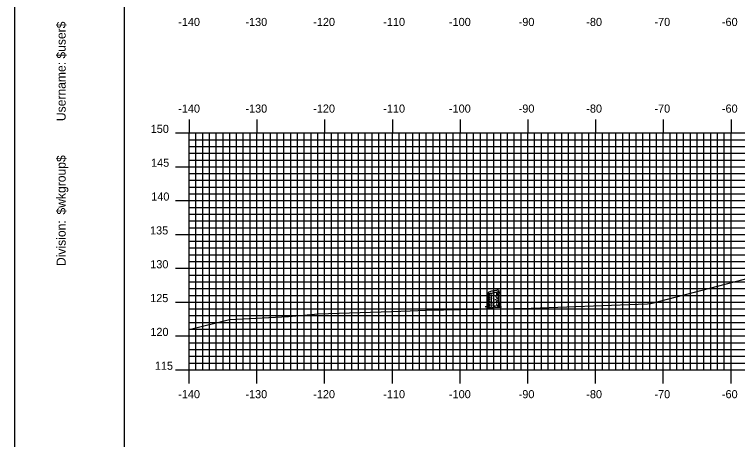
# Model space of a CAD drawing. Extents: x 851753 to 852097, y 364661 to 364881.
# Drawn here: x 851753.5 to 851860.2, y 364724.1 to 364786.9 of the extents above; entities that cross this region are included whole.
import ezdxf

# ---------------------------------------------------------------- set-up
doc = ezdxf.new("R2010")
doc.units = 0
for name, color, linetype in [('BORDER', 7, 'Continuous'), ('H_V ANNOTATION', 7, 'Continuous'), ('M_Trees_Conifer_Pay', 7, 'Continuous'), ('MAJOR', 7, 'Continuous'), ('MINOR', 7, 'Continuous'), ('PLOT BOUNDARY', 7, 'Continuous'), ('S_Roadway_Centerline', 7, 'Continuous')]:
    doc.layers.add(name, color=color, linetype=linetype)

msp = doc.modelspace()

# ---------------------------------------------------------------- linework, layer by layer
at = {"layer": 'BORDER'}
msp.add_lwpolyline([(851769.64, 364667.37), (852089.64, 364667.37), (852089.64, 364877.37), (851769.64, 364877.37)], close=True, dxfattribs=at)
at = {"layer": 'M_Trees_Conifer_Pay'}
for p, q in [((851823.36, 364744.01), (851823.36, 364745.73)), ((851823.41, 364745.69), (851823.41, 364745.22)), ((851823.47, 364745.68), (851823.47, 364745.58)), ((851823.59, 364745.67), (851823.59, 364745.44)), ((851823.81, 364745.69), (851823.81, 364745.52)), ((851824.61, 364745.73), (851824.61, 364745.53)), ((851824.84, 364745.93), (851824.84, 364745.71)), ((851824.84, 364745.62), (851824.84, 364745.57)), ((851824.95, 364745.99), (851824.95, 364745.83)), ((851824.95, 364745.76), (851824.95, 364745.63)), ((851825.02, 364744.42), (851825.02, 364746.06)), ((851823.41, 364745.15), (851823.41, 364744.85)), ((851823.41, 364744.8), (851823.41, 364744.31)), ((851823.47, 364745.51), (851823.47, 364745.3)), ((851823.47, 364745.25), (851823.47, 364745.05)), ((851823.47, 364745), (851823.47, 364744.66)), ((851823.47, 364744.61), (851823.47, 364744.47)), ((851823.59, 364745.4), (851823.59, 364745.32)), ((851823.59, 364744.92), (851823.59, 364744.78)), ((851823.81, 364745.29), (851823.81, 364745.05)), ((851823.81, 364744.8), (851823.81, 364744.65)), ((851823.81, 364744.61), (851823.81, 364744.44)), ((851824.22, 364745.46), (851824.22, 364745.36)), ((851824.22, 364744.85), (851824.22, 364744.77)), ((851824.22, 364744.75), (851824.22, 364744.6)), ((851824.61, 364745.48), (851824.61, 364745.39)), ((851824.61, 364745.04), (851824.61, 364744.93)), ((851824.61, 364744.57), (851824.61, 364744.42)), ((851824.89, 364745.43), (851824.84, 364745.37)), ((851824.84, 364745.24), (851824.84, 364745.1)), ((851824.84, 364744.99), (851824.84, 364744.88)), ((851824.84, 364744.75), (851824.84, 364744.61)), ((851824.95, 364745.45), (851824.95, 364745.11)), ((851824.95, 364745.07), (851824.95, 364744.91)), ((851824.95, 364744.86), (851824.95, 364744.65)), ((851824.95, 364744.62), (851824.95, 364744.54)), ((851823.41, 364744.25), (851823.41, 364744.01)), ((851823.47, 364744.37), (851823.47, 364744)), ((851823.59, 364744.51), (851823.59, 364744.37)), ((851823.59, 364744.11), (851823.59, 364744.01)), ((851823.59, 364743.61), (851823.75, 364743.68)), ((851823.81, 364744.16), (851823.81, 364744.01)), ((851824.03, 364743.55), (851823.9, 364743.61)), ((851824.22, 364744.31), (851824.22, 364744.15)), ((851824.61, 364744.19), (851824.61, 364744.1)), ((851824.84, 364744.38), (851824.84, 364744.21)), ((851824.95, 364744.5), (851824.95, 364744.33))]:
    msp.add_line(p, q, dxfattribs=at)
for points in [[(851824.84, 364745.56), (851824.88, 364745.49), (851824.93, 364745.54), (851824.98, 364745.61), (851825.08, 364745.81), (851825.14, 364745.85), (851825.17, 364745.86)], [(851824.86, 364745.31), (851824.89, 364745.43), (851824.96, 364745.55), (851824.99, 364745.62), (851825.06, 364745.76)], [(851825.07, 364745.79), (851825.15, 364745.8), (851825.22, 364745.7)], [(851823.54, 364745.03), (851823.53, 364745.13), (851823.58, 364745.11), (851823.58, 364745.01)], [(851824.68, 364744.63), (851824.69, 364744.56), (851824.74, 364744.57), (851824.73, 364744.73)], [(851824.81, 364745.52), (851824.78, 364745.44), (851824.77, 364745.37), (851824.8, 364745.31)], [(851825.02, 364744.42), (851825.08, 364744.15), (851825.09, 364743.88), (851825.15, 364743.75), (851825.29, 364743.72), (851825.06, 364743.69), (851825.06, 364743.69), (851825.06, 364743.64), (851825.31, 364743.54), (851825.03, 364743.56), (851824.68, 364743.58), (851824.36, 364743.57), (851824.36, 364743.65), (851824.22, 364743.57), (851824.03, 364743.55), (851824.05, 364743.48), (851823.78, 364743.52), (851823.56, 364743.5), (851823.27, 364743.51), (851823.56, 364743.57), (851823.59, 364743.61), (851823.43, 364743.67), (851823.19, 364743.68), (851822.95, 364743.68), (851823.29, 364743.74), (851823.33, 364743.82), (851823.36, 364744.01)], [(851823.41, 364743.96), (851823.39, 364743.88), (851823.37, 364743.79)], [(851823.49, 364743.94), (851823.49, 364743.82), (851823.44, 364743.73), (851823.43, 364743.67)], [(851823.65, 364743.96), (851823.65, 364743.83), (851823.56, 364743.73)], [(851823.88, 364743.72), (851823.94, 364743.82), (851823.97, 364743.96)], [(851824.36, 364743.65), (851824.44, 364743.8), (851824.45, 364743.9)], [(851824.61, 364744.02), (851824.62, 364743.9), (851824.7, 364743.85)], [(851824.89, 364743.63), (851824.88, 364743.77), (851824.8, 364743.9)], [(851824.85, 364744.13), (851824.93, 364744.02), (851824.93, 364743.85), (851825.06, 364743.69)], [(851824.95, 364744.27), (851824.96, 364744.13), (851825, 364744.06), (851825.01, 364743.86)]]:
    msp.add_lwpolyline(points, dxfattribs=at)
for centre, radius, start, end in [((851823.41, 364745.72), 0.0527, 146.7194, 156.5158), ((851823.39, 364745.73), 0.0314, 156.5158, 169.2194), ((851823.39, 364745.73), 0.0264, 169.2194, 180.0315), ((851823.38, 364745.73), 0.0226, 180.0315, 191.7194), ((851823.38, 364745.73), 0.0226, 191.7194, 203.4074), ((851823.39, 364745.73), 0.0264, 203.4074, 214.2194), ((851823.39, 364745.73), 0.0314, 214.2194, 226.923), ((851823.44, 364745.7), 0.0817, 132.3887, 146.7194), ((851823.41, 364745.75), 0.0527, 226.923, 236.7194), ((851823.55, 364745.58), 0.251, 124.2194, 132.3887), ((851823.42, 364745.77), 0.0817, 236.7194, 251.0501), ((851823.48, 364745.93), 0.251, 251.0501, 259.2194), ((851823.86, 364745.12), 0.802, 108.0594, 124.2194), ((851823.58, 364746.47), 0.802, 259.2194, 275.3794), ((851825.22, 364740.96), 5.18, 101.7194, 108.0594), ((851823.17, 364750.83), 5.18, 275.3794, 281.7194), ((851824.19, 364749.74), 4.12, 264.6955, 266.7331), ((851825.22, 364740.96), 5.18, 95.3794, 101.7194), ((851823.17, 364750.83), 5.18, 281.7194, 288.0594), ((851824.19, 364749.74), 4.12, 276.238, 278.1032), ((851824.81, 364745.32), 0.802, 79.2194, 95.3794), ((851824.53, 364746.67), 0.802, 288.0594, 304.2194), ((851824.69, 364746.22), 0.571, 278.1032, 284.3667), ((851824.69, 364746.38), 0.571, 284.4317, 292.4132), ((851824.69, 364746.22), 0.571, 297.0237, 300), ((851824.91, 364745.86), 0.251, 71.0501, 79.2194), ((851824.84, 364746.21), 0.251, 304.2194, 312.3887), ((851824.89, 364746.03), 0.172, 300, 311.2506), ((851824.89, 364745.88), 0.172, 300, 311.2506), ((851824.96, 364746.02), 0.0817, 56.7194, 71.0501), ((851824.95, 364746.09), 0.0817, 312.3887, 326.7194), ((851824.98, 364746.04), 0.0527, 46.923, 56.7194), ((851824.96, 364745.95), 0.0624, 311.2506, 330), ((851824.96, 364745.79), 0.0624, 311.2506, 330), ((851825, 364746.06), 0.0264, 23.4074, 34.2194), ((851824.99, 364746.06), 0.0314, 34.2194, 46.923), ((851825, 364746.06), 0.0226, 11.7194, 23.4074), ((851825, 364746.06), 0.0226, 0.0315, 11.7194), ((851824.99, 364746.06), 0.0314, 336.5158, 349.2194), ((851825, 364746.06), 0.0264, 349.2194, 0.0315), ((851824.97, 364746.07), 0.0527, 326.7194, 336.5158), ((851824.98, 364745.94), 0.0441, 330, 343.9485), ((851824.99, 364745.94), 0.0334, 343.9485, 354.2151), ((851824.99, 364745.78), 0.0334, 343.9485, 354.2151), ((851824.98, 364745.78), 0.0441, 330, 343.9485), ((851823.39, 364745.55), 0.0334, 163.9485, 180), ((851823.39, 364745.55), 0.0334, 180, 196.0515), ((851823.4, 364745.55), 0.0441, 196.0515, 210), ((851823.42, 364745.56), 0.0624, 210, 228.7494), ((851823.39, 364745.1), 0.0334, 163.9485, 180), ((851823.39, 364745.1), 0.0334, 180, 196.0515), ((851823.4, 364745.11), 0.0441, 196.0515, 210), ((851823.42, 364745.11), 0.0624, 210, 228.7494), ((851823.39, 364744.89), 0.0334, 163.9485, 180), ((851823.39, 364744.89), 0.0334, 180, 196.0515), ((851823.4, 364744.9), 0.0441, 196.0515, 210), ((851823.42, 364744.9), 0.0624, 210, 228.7494), ((851823.39, 364744.66), 0.0334, 163.9485, 180), ((851823.39, 364744.66), 0.0334, 180, 196.0515), ((851823.4, 364744.66), 0.0441, 196.0515, 210), ((851823.42, 364744.67), 0.0624, 210, 228.7494), ((851823.49, 364745.64), 0.172, 228.7494, 240), ((851823.49, 364745.2), 0.172, 228.7494, 240), ((851823.49, 364744.99), 0.172, 228.7494, 240), ((851823.49, 364744.75), 0.172, 228.7494, 240), ((851823.69, 364745.99), 0.571, 240, 240.3367), ((851823.69, 364745.54), 0.571, 240, 240.3367), ((851823.69, 364745.33), 0.571, 240, 246.8597), ((851823.69, 364745.1), 0.571, 240, 246.8597), ((851823.69, 364745.78), 0.571, 240, 247.0587), ((851823.69, 364745.99), 0.571, 246.8597, 257.9846), ((851823.69, 364745.33), 0.571, 259.2707, 261.8968), ((851824.19, 364748.85), 4.12, 261.8968, 263.1474), ((851824.19, 364749.06), 4.12, 264.081, 266.6676), ((851824.19, 364749.51), 4.12, 268.0751, 270), ((851824.19, 364749.51), 4.12, 270, 270.3581), ((851824.19, 364748.85), 4.12, 270, 270.3581), ((851824.19, 364748.85), 4.12, 273.1493, 275.4569), ((851824.19, 364749.3), 4.12, 273.7052, 275.9504), ((851824.19, 364749.51), 4.12, 275.7849, 277.0558), ((851824.19, 364749.06), 4.12, 277.6125, 278.1032), ((851824.69, 364745.54), 0.571, 278.1032, 286.9296), ((851824.69, 364745.78), 0.571, 284.4493, 297.0429), ((851824.69, 364745.1), 0.571, 285.3983, 297.1896), ((851824.69, 364745.54), 0.571, 297.1896, 300), ((851824.69, 364745.33), 0.571, 297.1896, 300), ((851824.89, 364745.2), 0.172, 300, 311.2506), ((851824.89, 364744.99), 0.172, 300, 311.2506), ((851824.96, 364745.11), 0.0624, 311.2506, 330), ((851824.96, 364744.9), 0.0624, 311.2506, 330), ((851824.99, 364745.34), 0.0334, 343.9485, 354.2151), ((851824.99, 364745.1), 0.0334, 343.9485, 354.2151), ((851824.98, 364745.11), 0.0441, 330, 343.9485), ((851824.99, 364744.89), 0.0334, 343.9485, 354.2151), ((851824.98, 364744.9), 0.0441, 330, 343.9485), ((851823.39, 364744.46), 0.0334, 163.9485, 180), ((851823.39, 364744.26), 0.0334, 163.9485, 180), ((851823.39, 364744.26), 0.0334, 180, 196.0515), ((851823.4, 364744.27), 0.0441, 196.0515, 210), ((851823.42, 364744.27), 0.0624, 210, 228.7494), ((851823.39, 364744.04), 0.0334, 163.9485, 180), ((851823.39, 364744.04), 0.0334, 180, 196.0515), ((851823.4, 364744.04), 0.0441, 196.0515, 210), ((851823.42, 364744.05), 0.0624, 210, 228.7494), ((851823.49, 364744.36), 0.172, 228.7494, 240), ((851823.49, 364744.14), 0.172, 228.7494, 240), ((851823.68, 364744.9), 0.571, 241.2369, 248.0268), ((851823.69, 364744.7), 0.571, 240, 246.8597), ((851823.69, 364744.48), 0.571, 240, 244.5314), ((851824.19, 364748), 4.12, 262.4438, 263.512), ((851824.19, 364748.42), 4.12, 263.4991, 265.8397), ((851824.19, 364748.61), 4.12, 264.716, 266.3193), ((851824.19, 364748.22), 4.12, 267.8117, 270), ((851824.19, 364748.22), 4.12, 270, 270.1328), ((851824.19, 364748.22), 4.12, 275.7849, 276.7896), ((851824.19, 364748), 4.12, 277.3684, 278.1032), ((851824.69, 364744.48), 0.571, 278.1032, 281.637), ((851824.69, 364744.7), 0.571, 288.5067, 297.2721), ((851824.69, 364744.9), 0.571, 289.2907, 300), ((851824.89, 364744.55), 0.172, 300, 311.2506), ((851824.89, 364744.14), 0.172, 300, 311.2506), ((851824.96, 364744.47), 0.0624, 311.2506, 330), ((851824.96, 364744.05), 0.0624, 311.2506, 330), ((851824.98, 364744.46), 0.0441, 330, 343.9485), ((851824.99, 364744.46), 0.0334, 343.9485, 354.2151), ((851824.99, 364744.04), 0.0334, 343.9485, 354.2151), ((851824.98, 364744.04), 0.0441, 330, 343.9485)]:
    msp.add_arc(centre, radius, start, end, dxfattribs=at)
at = {"layer": 'MAJOR'}
for p, q in [((851779.24, 364771.37), (851779.24, 364769.37)), ((851789.24, 364771.37), (851789.24, 364769.37)), ((851799.24, 364771.37), (851799.24, 364769.37)), ((851809.24, 364771.37), (851809.24, 364769.37)), ((851819.24, 364771.37), (851819.24, 364769.37)), ((851829.24, 364771.37), (851829.24, 364769.37)), ((851839.24, 364771.37), (851839.24, 364769.37)), ((851849.24, 364771.37), (851849.24, 364769.37)), ((851859.24, 364771.37), (851859.24, 364769.37)), ((851777.24, 364769.37), (851779.24, 364769.37)), ((851779.24, 364769.37), (852059.24, 364769.37)), ((851779.24, 364734.37), (851779.24, 364769.37)), ((851779.24, 364734.37), (851779.24, 364769.37)), ((851779.24, 364769.37), (852059.24, 364769.37)), ((851789.24, 364734.37), (851789.24, 364769.37)), ((851799.24, 364734.37), (851799.24, 364769.37)), ((851809.24, 364734.37), (851809.24, 364769.37)), ((851819.24, 364734.37), (851819.24, 364769.37)), ((851829.24, 364734.37), (851829.24, 364769.37)), ((851839.24, 364734.37), (851839.24, 364769.37)), ((851849.24, 364734.37), (851849.24, 364769.37)), ((851859.24, 364734.37), (851859.24, 364769.37)), ((851777.24, 364764.37), (851779.24, 364764.37)), ((851779.24, 364764.37), (852059.24, 364764.37)), ((851777.24, 364759.37), (851779.24, 364759.37)), ((851779.24, 364759.37), (852059.24, 364759.37)), ((851777.24, 364754.37), (851779.24, 364754.37)), ((851779.24, 364754.37), (852059.24, 364754.37)), ((851777.24, 364749.37), (851779.24, 364749.37)), ((851779.24, 364749.37), (852059.24, 364749.37)), ((851777.24, 364744.37), (851779.24, 364744.37)), ((851779.24, 364744.37), (852059.24, 364744.37)), ((851777.24, 364739.37), (851779.24, 364739.37)), ((851779.24, 364739.37), (852059.24, 364739.37)), ((851777.24, 364734.37), (851779.24, 364734.37)), ((851779.24, 364734.37), (852059.24, 364734.37)), ((851779.24, 364734.37), (852059.24, 364734.37)), ((851779.24, 364732.37), (851779.24, 364734.37)), ((851789.24, 364732.37), (851789.24, 364734.37)), ((851799.24, 364732.37), (851799.24, 364734.37)), ((851809.24, 364732.37), (851809.24, 364734.37)), ((851819.24, 364732.37), (851819.24, 364734.37)), ((851829.24, 364732.37), (851829.24, 364734.37)), ((851839.24, 364732.37), (851839.24, 364734.37)), ((851849.24, 364732.37), (851849.24, 364734.37)), ((851859.24, 364732.37), (851859.24, 364734.37))]:
    msp.add_line(p, q, dxfattribs=at)
at = {"layer": 'MINOR'}
for p, q in [((851780.24, 364734.37), (851780.24, 364769.37)), ((851781.24, 364734.37), (851781.24, 364769.37)), ((851782.24, 364734.37), (851782.24, 364769.37)), ((851783.24, 364734.37), (851783.24, 364769.37)), ((851784.24, 364734.37), (851784.24, 364769.37)), ((851785.24, 364734.37), (851785.24, 364769.37)), ((851786.24, 364734.37), (851786.24, 364769.37)), ((851787.24, 364734.37), (851787.24, 364769.37)), ((851788.24, 364734.37), (851788.24, 364769.37)), ((851790.24, 364734.37), (851790.24, 364769.37)), ((851791.24, 364734.37), (851791.24, 364769.37)), ((851792.24, 364734.37), (851792.24, 364769.37)), ((851793.24, 364734.37), (851793.24, 364769.37)), ((851794.24, 364734.37), (851794.24, 364769.37)), ((851795.24, 364734.37), (851795.24, 364769.37)), ((851796.24, 364734.37), (851796.24, 364769.37)), ((851797.24, 364734.37), (851797.24, 364769.37)), ((851798.24, 364734.37), (851798.24, 364769.37)), ((851800.24, 364734.37), (851800.24, 364769.37)), ((851801.24, 364734.37), (851801.24, 364769.37)), ((851802.24, 364734.37), (851802.24, 364769.37)), ((851803.24, 364734.37), (851803.24, 364769.37)), ((851804.24, 364734.37), (851804.24, 364769.37)), ((851805.24, 364734.37), (851805.24, 364769.37)), ((851806.24, 364734.37), (851806.24, 364769.37)), ((851807.24, 364734.37), (851807.24, 364769.37)), ((851808.24, 364734.37), (851808.24, 364769.37)), ((851810.24, 364734.37), (851810.24, 364769.37)), ((851811.24, 364734.37), (851811.24, 364769.37)), ((851812.24, 364734.37), (851812.24, 364769.37)), ((851813.24, 364734.37), (851813.24, 364769.37)), ((851814.24, 364734.37), (851814.24, 364769.37)), ((851815.24, 364734.37), (851815.24, 364769.37)), ((851816.24, 364734.37), (851816.24, 364769.37)), ((851817.24, 364734.37), (851817.24, 364769.37)), ((851818.24, 364734.37), (851818.24, 364769.37)), ((851820.24, 364734.37), (851820.24, 364769.37)), ((851821.24, 364734.37), (851821.24, 364769.37)), ((851822.24, 364734.37), (851822.24, 364769.37)), ((851823.24, 364734.37), (851823.24, 364769.37)), ((851824.24, 364734.37), (851824.24, 364769.37)), ((851825.24, 364734.37), (851825.24, 364769.37)), ((851826.24, 364734.37), (851826.24, 364769.37)), ((851827.24, 364734.37), (851827.24, 364769.37)), ((851828.24, 364734.37), (851828.24, 364769.37)), ((851830.24, 364734.37), (851830.24, 364769.37)), ((851831.24, 364734.37), (851831.24, 364769.37)), ((851832.24, 364734.37), (851832.24, 364769.37)), ((851833.24, 364734.37), (851833.24, 364769.37)), ((851834.24, 364734.37), (851834.24, 364769.37)), ((851835.24, 364734.37), (851835.24, 364769.37)), ((851836.24, 364734.37), (851836.24, 364769.37)), ((851837.24, 364734.37), (851837.24, 364769.37)), ((851838.24, 364734.37), (851838.24, 364769.37)), ((851840.24, 364734.37), (851840.24, 364769.37)), ((851841.24, 364734.37), (851841.24, 364769.37)), ((851842.24, 364734.37), (851842.24, 364769.37)), ((851843.24, 364734.37), (851843.24, 364769.37)), ((851844.24, 364734.37), (851844.24, 364769.37)), ((851845.24, 364734.37), (851845.24, 364769.37)), ((851846.24, 364734.37), (851846.24, 364769.37)), ((851847.24, 364734.37), (851847.24, 364769.37)), ((851848.24, 364734.37), (851848.24, 364769.37)), ((851850.24, 364734.37), (851850.24, 364769.37)), ((851851.24, 364734.37), (851851.24, 364769.37)), ((851852.24, 364734.37), (851852.24, 364769.37)), ((851853.24, 364734.37), (851853.24, 364769.37)), ((851854.24, 364734.37), (851854.24, 364769.37)), ((851855.24, 364734.37), (851855.24, 364769.37)), ((851856.24, 364734.37), (851856.24, 364769.37)), ((851857.24, 364734.37), (851857.24, 364769.37)), ((851858.24, 364734.37), (851858.24, 364769.37)), ((851779.24, 364768.37), (852059.24, 364768.37)), ((851779.24, 364768.37), (851781.25, 364768.37)), ((851779.24, 364767.37), (852059.24, 364767.37)), ((851779.24, 364767.37), (851781.25, 364767.37)), ((851779.24, 364766.37), (852059.24, 364766.37)), ((851779.24, 364766.37), (851781.25, 364766.37)), ((851779.24, 364765.37), (852059.24, 364765.37)), ((851779.24, 364765.37), (851781.25, 364765.37)), ((851779.24, 364763.37), (852059.24, 364763.37)), ((851779.24, 364763.37), (851781.25, 364763.37)), ((851779.24, 364762.37), (852059.24, 364762.37)), ((851779.24, 364762.37), (851781.25, 364762.37)), ((851779.24, 364761.37), (852059.24, 364761.37)), ((851779.24, 364761.37), (851781.25, 364761.37)), ((851779.24, 364760.37), (852059.24, 364760.37)), ((851779.24, 364760.37), (851781.25, 364760.37)), ((851779.24, 364758.37), (852059.24, 364758.37)), ((851779.24, 364758.37), (851781.25, 364758.37)), ((851779.24, 364757.37), (852059.24, 364757.37)), ((851779.24, 364757.37), (851781.25, 364757.37)), ((851779.24, 364756.37), (852059.24, 364756.37)), ((851779.24, 364756.37), (851781.25, 364756.37)), ((851779.24, 364755.37), (852059.24, 364755.37)), ((851779.24, 364755.37), (851781.25, 364755.37)), ((851779.24, 364753.37), (852059.24, 364753.37)), ((851779.24, 364753.37), (851781.25, 364753.37)), ((851779.24, 364752.37), (852059.24, 364752.37)), ((851779.24, 364752.37), (851781.25, 364752.37)), ((851779.24, 364751.37), (852059.24, 364751.37)), ((851779.24, 364751.37), (851781.25, 364751.37)), ((851779.24, 364750.37), (852059.24, 364750.37)), ((851779.24, 364750.37), (851781.25, 364750.37)), ((851779.24, 364748.37), (852059.24, 364748.37)), ((851779.24, 364748.37), (851781.25, 364748.37)), ((851779.24, 364747.37), (852059.24, 364747.37)), ((851779.24, 364747.37), (851781.25, 364747.37)), ((851779.24, 364746.37), (852059.24, 364746.37)), ((851779.24, 364746.37), (851781.25, 364746.37)), ((851779.24, 364745.37), (852059.24, 364745.37)), ((851779.24, 364745.37), (851781.25, 364745.37)), ((851779.24, 364743.37), (852059.24, 364743.37)), ((851779.24, 364743.37), (851781.25, 364743.37)), ((851779.24, 364742.37), (852059.24, 364742.37)), ((851779.24, 364742.37), (851781.25, 364742.37)), ((851779.24, 364741.37), (852059.24, 364741.37)), ((851779.24, 364741.37), (851781.25, 364741.37)), ((851779.24, 364740.37), (852059.24, 364740.37)), ((851779.24, 364740.37), (851781.25, 364740.37)), ((851779.24, 364738.37), (852059.24, 364738.37)), ((851779.24, 364738.37), (851781.25, 364738.37)), ((851779.24, 364737.37), (852059.24, 364737.37)), ((851779.24, 364737.37), (851781.25, 364737.37)), ((851779.24, 364736.37), (852059.24, 364736.37)), ((851779.24, 364736.37), (851781.25, 364736.37)), ((851779.24, 364735.37), (852059.24, 364735.37)), ((851779.24, 364735.37), (851781.25, 364735.37))]:
    msp.add_line(p, q, dxfattribs=at)
at = {"layer": 'PLOT BOUNDARY'}
msp.add_lwpolyline([(851753.46, 364661.25), (852093.46, 364661.25), (852093.46, 364881.25), (851753.46, 364881.25)], close=True, dxfattribs=at)
at = {"layer": 'S_Roadway_Centerline'}
msp.add_lwpolyline([(851779.24, 364740.33), (851785.18, 364741.78), (851793.93, 364742.23), (851798.31, 364742.64), (851809.09, 364743), (851811.88, 364743.09), (851814.16, 364743.17), (851829.74, 364743.49), (851845.53, 364744.07), (851846.88, 364744.13), (851847.38, 364744.15), (851864.82, 364748.68), (851871.1, 364751.41), (851878.27, 364755.23)], dxfattribs=at)

# ---------------------------------------------------------------- texts
at = {"layer": 'BORDER'}
for s, p in [('$user$', (851761.01, 364780.35)), ('Username:', (851761.01, 364771.11)), ('$wkgroup$', (851761.01, 364757.31)), ('Division:', (851761.01, 364749.7))]:
    msp.add_text(s, height=1.339, rotation=90, dxfattribs=at).set_placement(p)
at = {"layer": 'H_V ANNOTATION'}
for s, p in [('-140', (851777.63, 364785.17)), ('-130', (851787.55, 364785.17)), ('-120', (851797.56, 364785.17)), ('-110', (851807.9, 364785.17)), ('-100', (851817.6, 364785.17)), ('-90', (851827.89, 364785.17)), ('-80', (851837.87, 364785.17)), ('-70', (851847.93, 364785.17)), ('-60', (851857.89, 364785.17)), ('-140', (851777.63, 364772.37)), ('-130', (851787.55, 364772.37)), ('-120', (851797.56, 364772.37)), ('-110', (851807.9, 364772.37)), ('-100', (851817.6, 364772.37)), ('-90', (851827.89, 364772.37)), ('-80', (851837.87, 364772.37)), ('-70', (851847.93, 364772.37)), ('-60', (851857.89, 364772.37)), ('150', (851773.57, 364769.37)), ('145', (851773.62, 364764.37)), ('140', (851773.65, 364759.37)), ('135', (851773.47, 364754.37)), ('130', (851773.5, 364749.37)), ('125', (851773.49, 364744.37)), ('120', (851773.52, 364739.37)), ('115', (851774.18, 364734.37)), ('-140', (851777.63, 364730.17)), ('-130', (851787.55, 364730.17)), ('-120', (851797.56, 364730.17)), ('-110', (851807.9, 364730.17)), ('-100', (851817.6, 364730.17)), ('-90', (851827.89, 364730.17)), ('-80', (851837.87, 364730.17)), ('-70', (851847.93, 364730.17)), ('-60', (851857.89, 364730.17))]:
    msp.add_text(s, height=1.2, dxfattribs=at).set_placement(p)
at = {"layer": 'MAJOR'}
msp.add_text('-', height=0.012, dxfattribs=at).set_placement((851779.23, 364734.37))

doc.saveas('drawing.dxf')
